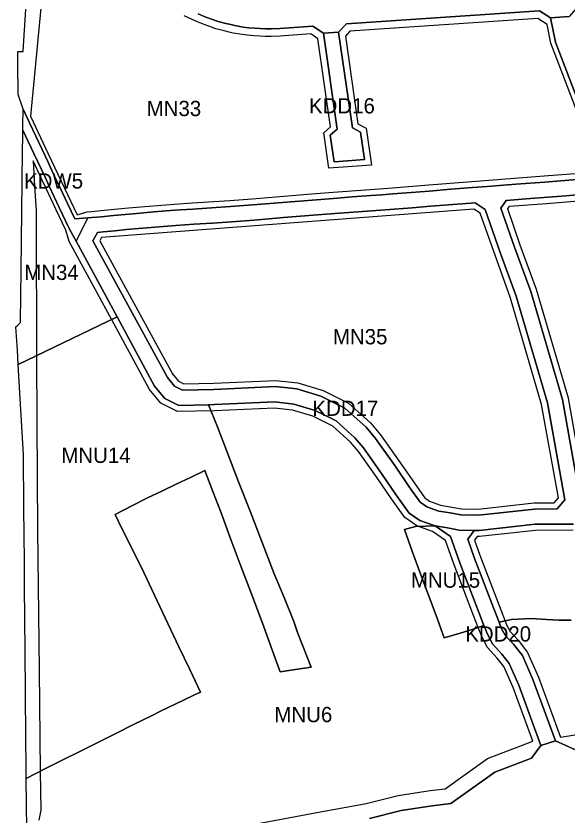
# Model space of a CAD drawing. Extents: x 7440055 to 7442242, y 5549003 to 5552256.
# Drawn here: x 7440571 to 7440932, y 5549569 to 5550092 of the extents above; entities that cross this region are included whole.
import ezdxf

# ---------------------------------------------------------------- set-up
doc = ezdxf.new("R2010")
doc.units = 0
for name, color, linetype in [('linie_rozgraniczajace', 7, 'Continuous'), ('linie_zabudowy_nieprzekraczalne', 7, 'Continuous'), ('oznaczenia_przeznaczen', 7, 'Continuous')]:
    doc.layers.add(name, color=color, linetype=linetype)

msp = doc.modelspace()

# ---------------------------------------------------------------- linework, layer by layer
at = {"layer": 'linie_rozgraniczajace'}
for points in [[(7440943.35, 5549985.58), (7440917.23, 5549983.48), (7440898.39, 5549982.03), (7440879.55, 5549980.59), (7440869.87, 5549979.85), (7440855.71, 5549978.73), (7440841.55, 5549977.62), (7440829.69, 5549976.68), (7440817.84, 5549975.75), (7440810.55, 5549975.2), (7440803.27, 5549974.64), (7440791.1, 5549973.71), (7440778.94, 5549972.78), (7440764.91, 5549971.69), (7440745.5, 5549970.15), (7440726.1, 5549968.61), (7440711.42, 5549967.44), (7440699.14, 5549966.63), (7440686.85, 5549965.81), (7440674.93, 5549965.03), (7440661.33, 5549963.89), (7440647.73, 5549962.76), (7440642.6, 5549962.33), (7440634.84, 5549961.56), (7440627.07, 5549960.8), (7440623.94, 5549960.49), (7440620.81, 5549960.18), (7440618.01, 5549959.97), (7440609.62, 5549959.32), (7440604.83, 5549969.45), (7440601.55, 5549976.39), (7440598.28, 5549983.34), (7440595.53, 5549989.17), (7440591.84, 5549996.99), (7440588.15, 5550004.8), (7440579.88, 5550022.3), (7440575.73, 5550031.09), (7440572.51, 5550040.68), (7440572.35, 5550061.06), (7440572.27, 5550068.98), (7440575.71, 5550069.01), (7440576.17, 5550076.23), (7440579.91, 5550133.83)], [(7440690.35, 5550093.6), (7440694.35, 5550091.85), (7440698.99, 5550090.12), (7440703.43, 5550088.66), (7440708.52, 5550087.24), (7440711.68, 5550086.49), (7440714.24, 5550085.94), (7440719.88, 5550084.96), (7440723.27, 5550084.51), (7440727.36, 5550084.13), (7440730.85, 5550083.9), (7440734.37, 5550083.78), (7440736.27, 5550083.77), (7440738.28, 5550083.8), (7440743.79, 5550084.03), (7440765.42, 5550085.49), (7440772.28, 5550080.96), (7440781.28, 5550018.15), (7440776.79, 5550014.18), (7440779.28, 5549996.78), (7440782.53, 5549997.02), (7440799.27, 5549998.28), (7440796.71, 5550016.2), (7440791.26, 5550018.97), (7440782.28, 5550081.64), (7440787.47, 5550086.98), (7440913.88, 5550095.55), (7440921.08, 5550091.06), (7440924.17, 5550075.14), (7440955.39, 5549993.61)], [(7440937.99, 5550097.18), (7440933.14, 5550091.88), (7440921.08, 5550091.06), (7440913.88, 5550095.55), (7440787.47, 5550086.98), (7440782.28, 5550081.64), (7440772.28, 5550080.96), (7440765.42, 5550085.49), (7440743.79, 5550084.03), (7440738.28, 5550083.8), (7440736.27, 5550083.77)], [(7440736.27, 5550083.77), (7440734.37, 5550083.78), (7440730.85, 5550083.9), (7440727.36, 5550084.13), (7440723.27, 5550084.51), (7440719.88, 5550084.96), (7440714.24, 5550085.94), (7440711.68, 5550086.49), (7440708.52, 5550087.24), (7440703.43, 5550088.66), (7440698.99, 5550090.12), (7440694.35, 5550091.85), (7440690.35, 5550093.6)], [(7440955.39, 5549993.61), (7440924.17, 5550075.14), (7440921.08, 5550091.06), (7440933.14, 5550091.88)], [(7440936, 5549759.56), (7440910.98, 5549759.5), (7440874.28, 5549755.43), (7440871.06, 5549755.52), (7440861.3, 5549755.77), (7440853.57, 5549757.12), (7440845.5, 5549758.42), (7440835.4, 5549762.02), (7440828.46, 5549766.84), (7440820.19, 5549778.38), (7440810.89, 5549792.19), (7440798.52, 5549809.49), (7440793, 5549816.07), (7440780.73, 5549827.15), (7440766.96, 5549834.06), (7440752.9, 5549838.23), (7440740.54, 5549839.59), (7440700.97, 5549837.82), (7440697.01, 5549837.74), (7440677.76, 5549837.33), (7440668.43, 5549841.94), (7440661.86, 5549850), (7440637.31, 5549895.23), (7440610.43, 5549944.77), (7440618.01, 5549959.97), (7440620.81, 5549960.18), (7440623.94, 5549960.49), (7440627.07, 5549960.8), (7440634.84, 5549961.56), (7440642.6, 5549962.33), (7440647.73, 5549962.76), (7440661.33, 5549963.89), (7440674.93, 5549965.03), (7440686.85, 5549965.81), (7440699.14, 5549966.63), (7440711.42, 5549967.44), (7440726.1, 5549968.61), (7440745.5, 5549970.15), (7440764.91, 5549971.69), (7440778.94, 5549972.78), (7440791.1, 5549973.71), (7440803.27, 5549974.64), (7440810.55, 5549975.2), (7440817.84, 5549975.75), (7440829.69, 5549976.68), (7440841.55, 5549977.62), (7440855.71, 5549978.73), (7440869.87, 5549979.85), (7440879.55, 5549980.59), (7440898.39, 5549982.03), (7440917.23, 5549983.48), (7440943.35, 5549985.58)], [(7440951.18, 5549976.19), (7440931.08, 5549974.56), (7440904.95, 5549972.51), (7440891.9, 5549971.51), (7440888.56, 5549966.4), (7440897.45, 5549940.84), (7440908.02, 5549911.96), (7440928.76, 5549841.19), (7440940.71, 5549774.91)], [(7440578.2, 5549559.87), (7440577.85, 5549593.22), (7440583.7, 5549596.19), (7440589.55, 5549599.15), (7440601.25, 5549605.04), (7440612.95, 5549610.92), (7440624.66, 5549616.75), (7440636.36, 5549622.58), (7440648.06, 5549628.41), (7440659.77, 5549634.24), (7440665.62, 5549637.15), (7440671.47, 5549640.07), (7440679.87, 5549644.08), (7440688.27, 5549648.1), (7440691.78, 5549649.58), (7440684.79, 5549664.39), (7440677.69, 5549679.4), (7440663.51, 5549709.43), (7440658.23, 5549720.52), (7440652.95, 5549731.6), (7440648.72, 5549740.15), (7440644.48, 5549748.71), (7440640.25, 5549757.27), (7440636.01, 5549765.83), (7440647.33, 5549771.85), (7440657.18, 5549776.82), (7440666.53, 5549781.29), (7440675.88, 5549785.76), (7440685.24, 5549790.23), (7440694.6, 5549794.7), (7440699.95, 5549780.89), (7440705.3, 5549767.08), (7440711.82, 5549749.63), (7440718.34, 5549732.19), (7440725.81, 5549712.27), (7440733.28, 5549692.35), (7440740.96, 5549671.27), (7440743.97, 5549662.94), (7440754.13, 5549664.45), (7440764.28, 5549665.96), (7440755.41, 5549688.74), (7440752.9, 5549696), (7440746.53, 5549711.51), (7440740.16, 5549727.02), (7440732.23, 5549747.51), (7440724.29, 5549768), (7440716.82, 5549787.37), (7440709.36, 5549806.74), (7440702.89, 5549823.28), (7440697.01, 5549837.74), (7440700.97, 5549837.82), (7440740.54, 5549839.59), (7440752.9, 5549838.23), (7440766.96, 5549834.06), (7440780.73, 5549827.15), (7440793, 5549816.07), (7440798.52, 5549809.49), (7440810.89, 5549792.19), (7440820.19, 5549778.38), (7440828.46, 5549766.84), (7440835.4, 5549762.02), (7440845.5, 5549758.42), (7440832.71, 5549758.05), (7440825.4, 5549756.15), (7440830.75, 5549741.27), (7440836.1, 5549726.4), (7440841.1, 5549713.16), (7440846.09, 5549699.92), (7440851.45, 5549685.23), (7440861.84, 5549688.36), (7440869.66, 5549690.71), (7440877.44, 5549693.19), (7440877.49, 5549693.07), (7440879.45, 5549687.93), (7440883.06, 5549681.17), (7440889.21, 5549674.54), (7440893.9, 5549668.43), (7440900.18, 5549654.27), (7440914.7, 5549614.65), (7440908.45, 5549606.4), (7440884.44, 5549597.32), (7440855.84, 5549576.74), (7440843.5, 5549575.3), (7440823.23, 5549572.15), (7440802.48, 5549567)], [(7440934.53, 5549696.82), (7440926.69, 5549696.68), (7440918.47, 5549697.17), (7440908.41, 5549697.77), (7440895.52, 5549697.1), (7440887.27, 5549695.5), (7440883.69, 5549704.87), (7440871.04, 5549737.85), (7440866.78, 5549749.83), (7440871.06, 5549755.52), (7440874.28, 5549755.43), (7440910.98, 5549759.5), (7440936, 5549759.56)], [(7440937.73, 5549611.73), (7440924.18, 5549617.76), (7440909.45, 5549658.02), (7440902.56, 5549673.57), (7440896.86, 5549681), (7440891.27, 5549687.02), (7440888.79, 5549691.5), (7440887.27, 5549695.5), (7440895.52, 5549697.1), (7440908.41, 5549697.77), (7440918.47, 5549697.17), (7440926.69, 5549696.68), (7440934.53, 5549696.82)], [(7440802.48, 5549567), (7440823.23, 5549572.15), (7440843.5, 5549575.3), (7440855.84, 5549576.74), (7440884.44, 5549597.32), (7440908.45, 5549606.4), (7440914.7, 5549614.65), (7440924.18, 5549617.76), (7440937.73, 5549611.73), (7440959.03, 5549612.31), (7440997, 5549599.66), (7441094.31, 5549616.16), (7441149.75, 5549626.01), (7441179.57, 5549631.34), (7441206.47, 5549636.19), (7441246.5, 5549643.08), (7441303.43, 5549652.3), (7441394.72, 5549667.37), (7441442.22, 5549675.26)]]:
    msp.add_lwpolyline(points, dxfattribs=at)
for points in [[(7440772.28, 5550080.96), (7440782.28, 5550081.64), (7440791.26, 5550018.97), (7440796.71, 5550016.2), (7440799.27, 5549998.28), (7440782.53, 5549997.02), (7440779.28, 5549996.78), (7440776.79, 5550014.18), (7440781.28, 5550018.15)], [(7440575.56, 5550017.4), (7440575.6, 5550020.31), (7440575.73, 5550031.09), (7440579.88, 5550022.3), (7440588.15, 5550004.8), (7440591.84, 5549996.99), (7440595.53, 5549989.17), (7440598.28, 5549983.34), (7440601.55, 5549976.39), (7440604.83, 5549969.45), (7440609.62, 5549959.32), (7440618.01, 5549959.97), (7440610.43, 5549944.77), (7440605.96, 5549953.02), (7440599.41, 5549966.89), (7440592.85, 5549980.78), (7440590.1, 5549986.61), (7440582.72, 5550002.24)], [(7440571.09, 5549888.8), (7440572.52, 5549890.14), (7440573.95, 5549891.47), (7440573.97, 5549892.34), (7440574.39, 5549925.54), (7440574.89, 5549964.53), (7440575.38, 5550003.51), (7440575.42, 5550006.91), (7440575.47, 5550010.31), (7440575.53, 5550015.31), (7440575.56, 5550017.4), (7440582.72, 5550002.24), (7440590.1, 5549986.61), (7440592.85, 5549980.78), (7440599.41, 5549966.89), (7440605.96, 5549953.02), (7440610.43, 5549944.77), (7440637.31, 5549895.23), (7440572.53, 5549864), (7440571.98, 5549873.48)], [(7440888.56, 5549966.4), (7440891.9, 5549971.51), (7440904.95, 5549972.51), (7440931.08, 5549974.56), (7440951.18, 5549976.19), (7440958.2, 5549976.76), (7440965.97, 5549972.37), (7440987.07, 5549929.99), (7441000.33, 5549906.48), (7441055.37, 5549815.55), (7441060.84, 5549802.98), (7441064.74, 5549787.25), (7441066.52, 5549775.2), (7441059.61, 5549769.53), (7441039.41, 5549768.65), (7441018.11, 5549767.68), (7440986.73, 5549765.88), (7440962.89, 5549766.41), (7440947.63, 5549768.24), (7440940.71, 5549774.91), (7440928.76, 5549841.19), (7440908.02, 5549911.96), (7440897.45, 5549940.84)], [(7440621.44, 5549945.04), (7440670.2, 5549855.6), (7440674.81, 5549849.94), (7440680, 5549847.38), (7440700.64, 5549847.82), (7440740.86, 5549849.61), (7440754.88, 5549848.07), (7440770.66, 5549843.39), (7440786.43, 5549835.48), (7440800.21, 5549823.03), (7440806.43, 5549815.63), (7440819.11, 5549797.9), (7440828.41, 5549784.09), (7440835.59, 5549774.07), (7440840.01, 5549770.99), (7440847.99, 5549768.14), (7440855.23, 5549766.98), (7440862.3, 5549765.74), (7440873.86, 5549765.45), (7440910.42, 5549769.5), (7440925.32, 5549769.54), (7440930.43, 5549775.58), (7440919.02, 5549838.89), (7440898.52, 5549908.84), (7440888.03, 5549937.48), (7440878.24, 5549965.62), (7440871.62, 5549969.95), (7440856.97, 5549968.8), (7440842.33, 5549967.65), (7440830.47, 5549966.72), (7440818.61, 5549965.78), (7440804.03, 5549964.67), (7440779.7, 5549962.81), (7440765.69, 5549961.73), (7440746.29, 5549960.18), (7440726.89, 5549958.64), (7440712.15, 5549957.47), (7440699.83, 5549956.65), (7440687.51, 5549955.84), (7440681.59, 5549955.45), (7440675.68, 5549955.06), (7440662.12, 5549953.93), (7440648.56, 5549952.79), (7440643.51, 5549952.37), (7440635.78, 5549951.61), (7440628.05, 5549950.85), (7440624.43, 5549950.49)], [(7440621.44, 5549945.04), (7440624.43, 5549950.49), (7440628.05, 5549950.85), (7440635.78, 5549951.61), (7440643.51, 5549952.37), (7440648.56, 5549952.79), (7440662.12, 5549953.93), (7440675.68, 5549955.06), (7440681.59, 5549955.45), (7440687.51, 5549955.84), (7440699.83, 5549956.65), (7440712.15, 5549957.47), (7440726.89, 5549958.64), (7440746.29, 5549960.18), (7440765.69, 5549961.73), (7440779.7, 5549962.81), (7440804.03, 5549964.67), (7440818.61, 5549965.78), (7440830.47, 5549966.72), (7440842.33, 5549967.65), (7440856.97, 5549968.8), (7440871.62, 5549969.95), (7440878.24, 5549965.62), (7440888.03, 5549937.48), (7440898.52, 5549908.84), (7440919.02, 5549838.89), (7440930.43, 5549775.58), (7440925.32, 5549769.54), (7440910.42, 5549769.5), (7440873.86, 5549765.45), (7440862.3, 5549765.74), (7440855.23, 5549766.98), (7440847.99, 5549768.14), (7440840.01, 5549770.99), (7440835.59, 5549774.07), (7440828.41, 5549784.09), (7440819.11, 5549797.9), (7440806.43, 5549815.63), (7440800.21, 5549823.03), (7440786.43, 5549835.48), (7440770.66, 5549843.39), (7440754.88, 5549848.07), (7440740.86, 5549849.61), (7440700.64, 5549847.82), (7440680, 5549847.38), (7440674.81, 5549849.94), (7440670.2, 5549855.6)], [(7440577.85, 5549593.22), (7440577.85, 5549593.42), (7440577.49, 5549626.98), (7440577.36, 5549642.3), (7440577.24, 5549655.93), (7440577.12, 5549669.57), (7440577.02, 5549681.31), (7440576.92, 5549693.05), (7440576.83, 5549703.16), (7440576.74, 5549713.28), (7440576.56, 5549735.24), (7440576.26, 5549770.08), (7440575.95, 5549804.92), (7440572.53, 5549864), (7440637.31, 5549895.23), (7440661.86, 5549850), (7440668.43, 5549841.94), (7440677.76, 5549837.33), (7440697.01, 5549837.74), (7440702.89, 5549823.28), (7440709.36, 5549806.74), (7440716.82, 5549787.37), (7440724.29, 5549768), (7440732.23, 5549747.51), (7440740.16, 5549727.02), (7440746.53, 5549711.51), (7440752.9, 5549696), (7440755.41, 5549688.74), (7440764.28, 5549665.96), (7440754.13, 5549664.45), (7440743.97, 5549662.94), (7440740.96, 5549671.27), (7440733.28, 5549692.35), (7440725.81, 5549712.27), (7440718.34, 5549732.19), (7440711.82, 5549749.63), (7440705.3, 5549767.08), (7440699.95, 5549780.89), (7440694.6, 5549794.7), (7440685.24, 5549790.23), (7440675.88, 5549785.76), (7440666.53, 5549781.29), (7440657.18, 5549776.82), (7440647.33, 5549771.85), (7440636.01, 5549765.83), (7440640.25, 5549757.27), (7440644.48, 5549748.71), (7440648.72, 5549740.15), (7440652.95, 5549731.6), (7440658.23, 5549720.52), (7440663.51, 5549709.43), (7440677.69, 5549679.4), (7440684.79, 5549664.39), (7440691.78, 5549649.58), (7440688.27, 5549648.1), (7440679.87, 5549644.08), (7440671.47, 5549640.07), (7440665.62, 5549637.15), (7440659.77, 5549634.24), (7440648.06, 5549628.41), (7440636.36, 5549622.58), (7440624.66, 5549616.75), (7440612.95, 5549610.92), (7440601.25, 5549605.04), (7440589.55, 5549599.15), (7440583.7, 5549596.19)], [(7440825.4, 5549756.15), (7440832.71, 5549758.05), (7440845.5, 5549758.42), (7440855.59, 5549751.46), (7440861.66, 5549734.38), (7440874.35, 5549701.3), (7440877.44, 5549693.19), (7440869.66, 5549690.71), (7440861.84, 5549688.36), (7440851.45, 5549685.23), (7440846.09, 5549699.92), (7440841.1, 5549713.16), (7440836.1, 5549726.4), (7440830.75, 5549741.27)], [(7440845.5, 5549758.42), (7440853.57, 5549757.12), (7440861.3, 5549755.77), (7440871.06, 5549755.52), (7440866.78, 5549749.83), (7440871.04, 5549737.85), (7440883.69, 5549704.87), (7440887.27, 5549695.5), (7440888.79, 5549691.5), (7440891.27, 5549687.02), (7440896.86, 5549681), (7440902.56, 5549673.57), (7440909.45, 5549658.02), (7440924.18, 5549617.76), (7440914.7, 5549614.65), (7440900.18, 5549654.27), (7440893.9, 5549668.43), (7440889.21, 5549674.54), (7440883.06, 5549681.17), (7440879.45, 5549687.93), (7440877.49, 5549693.07), (7440877.44, 5549693.19), (7440874.35, 5549701.3), (7440861.66, 5549734.38), (7440855.59, 5549751.46)]]:
    msp.add_lwpolyline(points, close=True, dxfattribs=at)
at = {"layer": 'linie_zabudowy_nieprzekraczalne'}
for points in [[(7440587.82, 5550101.87), (7440580.58, 5550026.69), (7440592.25, 5550001.96), (7440611.14, 5549961.94), (7440617.71, 5549963.95), (7440620.46, 5549964.17), (7440626.68, 5549964.78), (7440642.24, 5549966.31), (7440647.39, 5549966.74), (7440674.64, 5549969.02), (7440686.59, 5549969.81), (7440711.13, 5549971.43), (7440725.78, 5549972.6), (7440764.6, 5549975.68), (7440778.63, 5549976.77), (7440802.97, 5549978.63), (7440817.53, 5549979.74), (7440841.23, 5549981.6), (7440869.56, 5549983.83), (7440916.91, 5549987.47), (7440943.03, 5549989.57)], [(7440952.22, 5549993.51), (7440921.27, 5550074.31), (7440918.9, 5550086.53), (7440912.61, 5550090.45), (7440789.72, 5550082.13), (7440786.7, 5550079.01), (7440794.92, 5550021.59), (7440800.37, 5550018.83), (7440803.84, 5549994.61), (7440775.86, 5549992.51), (7440772.53, 5550015.75), (7440777.01, 5550019.71), (7440768.77, 5550077.29), (7440764.07, 5550080.39), (7440744.06, 5550079.03), (7440738.42, 5550078.81), (7440736.3, 5550078.77), (7440734.27, 5550078.78), (7440730.61, 5550078.91), (7440726.97, 5550079.14), (7440722.7, 5550079.54), (7440719.12, 5550080.02), (7440713.29, 5550081.03), (7440710.58, 5550081.61), (7440707.27, 5550082.4), (7440701.97, 5550083.87), (7440697.33, 5550085.41), (7440692.48, 5550087.21), (7440688.29, 5550089.04), (7440681.22, 5550092.35)], [(7440729.69, 5549563.74), (7440767.96, 5549570.89), (7440800.38, 5549576.78), (7440821.26, 5549581.97), (7440842.16, 5549585.21), (7440852.11, 5549586.37), (7440879.67, 5549606.21), (7440909.46, 5549617.47), (7440909.46, 5549617.47), (7440896.47, 5549652.76), (7440890.43, 5549666.37), (7440886.15, 5549671.96), (7440879.76, 5549678.85), (7440876.03, 5549686.06), (7440873.67, 5549691.92), (7440870.61, 5549699.87), (7440864.26, 5549716.43), (7440857.91, 5549732.99), (7440852.25, 5549748.9), (7440843.66, 5549754.83), (7440833.56, 5549758.43), (7440825.62, 5549763.95), (7440816.91, 5549776.1), (7440807.61, 5549789.91), (7440795.36, 5549807.04), (7440790.11, 5549813.29), (7440778.45, 5549823.82), (7440765.49, 5549830.33), (7440752.11, 5549834.29), (7440740.41, 5549835.58), (7440701.1, 5549833.82), (7440676.87, 5549833.31), (7440665.88, 5549838.74), (7440658.52, 5549847.77), (7440633.79, 5549893.32), (7440605.92, 5549944.69), (7440603.73, 5549951.89), (7440597.15, 5549965.82), (7440590.59, 5549979.71), (7440587.84, 5549985.54), (7440582.27, 5549997.36), (7440582.27, 5549997.36), (7440582.27, 5549997.36), (7440583.26, 5549980.98), (7440584.24, 5549964.61), (7440584.37, 5549930.48), (7440584.5, 5549896.36), (7440584.62, 5549869.83), (7440584.79, 5549826.03), (7440585.08, 5549755.7), (7440586.18, 5549664.11), (7440586.9, 5549597.81), (7440587.27, 5549572.52), (7440586.11, 5549565.96)], [(7441063.13, 5549777.59), (7441058.11, 5549773.47), (7441017.9, 5549771.67), (7440986.66, 5549769.89), (7440963.18, 5549770.4), (7440949.44, 5549772.05), (7440944.41, 5549776.89), (7440932.66, 5549842.11), (7440911.82, 5549913.21), (7440901.22, 5549942.18), (7440892.98, 5549965.86), (7440894.17, 5549967.67), (7440918.33, 5549969.52), (7440957.32, 5549972.66), (7440964.4, 5549968.79), (7440968.56, 5549960.44), (7440991.08, 5549916.78), (7441025.28, 5549859.47), (7441052.7, 5549814.17), (7441057.99, 5549802.02), (7441061.79, 5549786.66), (7441063.13, 5549777.59)], [(7440673.3, 5549858.12), (7440677.36, 5549853.14), (7440680.89, 5549851.4), (7440700.51, 5549851.81), (7440740.99, 5549853.62), (7440755.68, 5549852.01), (7440772.13, 5549847.13), (7440788.7, 5549838.81), (7440803.1, 5549825.81), (7440809.59, 5549818.08), (7440822.38, 5549800.2), (7440838.46, 5549776.94), (7440841.86, 5549774.58), (7440849.01, 5549772.03), (7440862.68, 5549769.73), (7440873.69, 5549769.45), (7440910.19, 5549773.5), (7440923.46, 5549773.53), (7440926.15, 5549776.73), (7440915.12, 5549837.98), (7440894.71, 5549907.6), (7440874.93, 5549963.03), (7440870.73, 5549965.75), (7440627.16, 5549947.16), (7440626, 5549945.03), (7440649.33, 5549902.23), (7440673.71, 5549857.51)], [(7440935.77, 5549755.56), (7440911.21, 5549755.5), (7440874.45, 5549751.43), (7440873.01, 5549751.46), (7440871.27, 5549749.14), (7440874.79, 5549739.23), (7440887.42, 5549706.3), (7440892.43, 5549693.19), (7440894.54, 5549689.39), (7440899.92, 5549683.58), (7440906.02, 5549675.63), (7440913.16, 5549659.52), (7440927.56, 5549620.28)], [(7440927.56, 5549620.28), (7440936.97, 5549621.71), (7440960.51, 5549622.35), (7440997.79, 5549609.94), (7441092.59, 5549626.01), (7441147.99, 5549635.86), (7441177.8, 5549641.18), (7441204.74, 5549646.04), (7441244.85, 5549652.94), (7441301.82, 5549662.16), (7441393.09, 5549677.24), (7441440.55, 5549685.12)]]:
    msp.add_lwpolyline(points, dxfattribs=at)

# ---------------------------------------------------------------- texts
at = {"layer": 'oznaczenia_przeznaczen'}
for s, p in [('MN33', (7440656.65, 5550026.64)), ('KDD16', (7440762.9, 5550028.38)), ('KDW5', (7440576.4, 5549979.22)), ('MN34', (7440576.49, 5549919.4)), ('MN35', (7440778.56, 5549877.28)), ('KDD17', (7440765.17, 5549830.48)), ('MNU14', (7440600.8, 5549799.65)), ('MNU15', (7440829.58, 5549717.99)), ('KDD20', (7440865.18, 5549682.77)), ('MNU6', (7440740.26, 5549630))]:
    msp.add_text(s, height=10, dxfattribs=at).set_placement(p)

doc.saveas('drawing.dxf')
